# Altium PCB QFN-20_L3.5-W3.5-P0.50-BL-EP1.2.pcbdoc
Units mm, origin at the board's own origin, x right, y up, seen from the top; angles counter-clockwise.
Board outline 16.81 x 17.12 mm, 2 copper layers (Top Layer, Bottom Layer), stack 0 mm thick; 1 components, 0 nets, 21 pads, 0 vias.
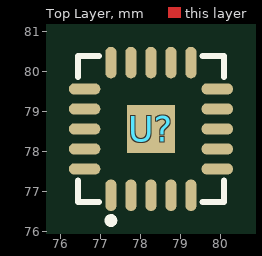
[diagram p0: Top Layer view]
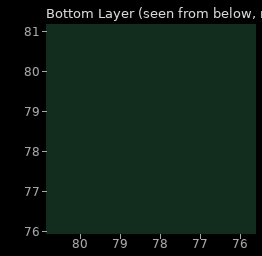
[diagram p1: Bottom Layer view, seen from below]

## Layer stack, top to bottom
Top Layer: signal copper (thickness not stored)
Bottom Layer: signal copper (thickness not stored)

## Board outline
86.655,69.85 69.85,69.85 69.85,86.973 86.655,86.973

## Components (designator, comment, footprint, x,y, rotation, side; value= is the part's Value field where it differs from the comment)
U? "" QFN-20_L3.5-W3.5-P0.50-BL-EP1.2 78.253,78.571 r0 top

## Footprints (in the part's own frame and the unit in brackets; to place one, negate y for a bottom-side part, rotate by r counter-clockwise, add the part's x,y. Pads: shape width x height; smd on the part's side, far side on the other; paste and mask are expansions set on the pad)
QFN-20_L3.5-W3.5-P0.50-BL-EP1.2 [mm]
  oval 0.28x0.79 smd: 1(-1,-1.658) 2(-0.5,-1.658) 3(0,-1.658) 4(0.5,-1.658) 5(1,-1.658) 11(1,1.658) 12(0.5,1.658) 13(0,1.658) 14(-0.5,1.658) 15(-1,1.658)
  oval 0.79x0.28 smd: 6(1.658,-1) 7(1.658,-0.5) 8(1.658,0) 9(1.658,0.5) 10(1.658,1) 16(-1.658,1) 17(-1.658,0.5) 18(-1.658,0) 19(-1.658,-0.5) 20(-1.658,-1)
  rect 1.2x1.2 smd: 21(0,0)
  silkscreen extent -1.83,-2.37 1.83,1.83

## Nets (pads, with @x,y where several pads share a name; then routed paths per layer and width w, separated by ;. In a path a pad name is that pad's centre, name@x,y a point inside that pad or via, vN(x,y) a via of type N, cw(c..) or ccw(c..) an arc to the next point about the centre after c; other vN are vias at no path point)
pads on no net: U?.1 U?.2 U?.3 U?.4 U?.5 U?.6 U?.7 U?.8 U?.9 U?.10 U?.11 U?.12 U?.13 U?.14 U?.15 U?.16 U?.17 U?.18 U?.19 U?.20 U?.21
